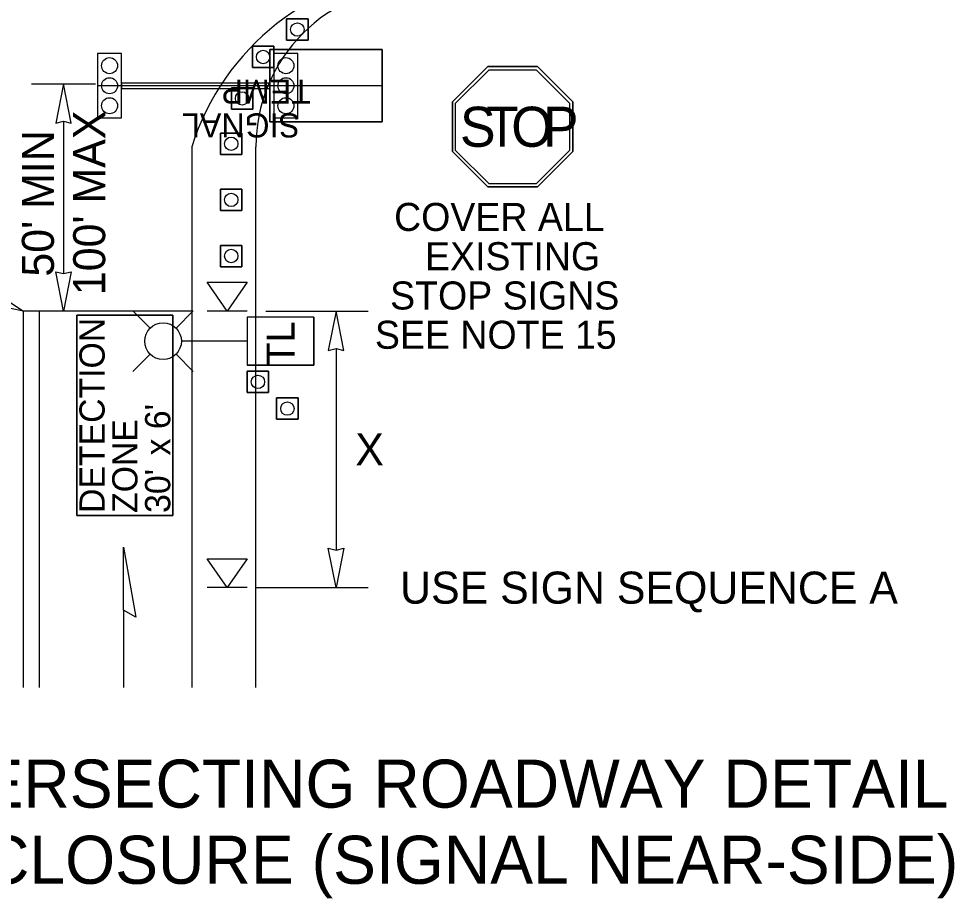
# Model space of a CAD drawing. Extents: x 99979.8 to 100075.7, y 99995 to 100010.7.
# Drawn here: x 100042.093 to 100044.428, y 100001.75 to 100003.944 of the extents above; entities that cross this region are included whole.
import ezdxf

# ---------------------------------------------------------------- set-up
doc = ezdxf.new("R2010")
doc.units = 0
for name, color, linetype in [('RD_ED_ShoulderPavedEdge', 7, 'Continuous'), ('RD_MK_LineDblYellowCenter', 7, 'Continuous'), ('RD_MK_LineEdgeWhite', 7, 'Continuous'), ('RD_MK_LineStop', 7, 'Continuous'), ('SH_DE_DetailHeading2Text', 7, 'Continuous'), ('TR_SN_ConstructionSigns', 7, 'Continuous'), ('TR_WZ_PortableLightStandard', 7, 'Continuous'), ('TR_WZ_PortableSignMountBlk-Org', 7, 'Continuous'), ('TR_WZ_PortableSignMountBlk-Wht', 7, 'Continuous'), ('TR_WZ_TempSignal', 7, 'Continuous'), ('TR_WZ_TrafficCone', 7, 'Continuous'), ('TR_WZ_WorkZoneDetails', 7, 'Continuous'), ('TR_WZ_WorkZoneTextCurrent', 7, 'Continuous')]:
    doc.layers.add(name, color=color, linetype=linetype)

msp = doc.modelspace()

# ---------------------------------------------------------------- linework, layer by layer
at = {"layer": 'RD_ED_ShoulderPavedEdge'}
msp.add_lwpolyline([(100042.685, 100002.2759), (100042.685, 100003.6249)], dxfattribs=at)
msp.add_arc((100043.085, 100003.6249), 0.4, 90, 180, dxfattribs=at)
at = {"layer": 'RD_MK_LineDblYellowCenter'}
for p, q in [((100042.105, 100002.2759), (100042.105, 100003.2149)), ((100042.145, 100002.2759), (100042.145, 100003.2149))]:
    msp.add_line(p, q, dxfattribs=at)
at = {"layer": 'RD_MK_LineEdgeWhite'}
msp.add_line((100042.525, 100003.6249), (100042.525, 100002.2759), dxfattribs=at)
msp.add_arc((100043.1265, 100003.4357), 0.6306, 93.7766, 162.5378, dxfattribs=at)
at = {"layer": 'RD_MK_LineStop'}
msp.add_line((100042.525, 100003.2149), (100042.105, 100003.2149), dxfattribs=at)
at = {"layer": 'TR_SN_ConstructionSigns'}
for p, q in [((100043.2637, 100003.8249), (100043.1758, 100003.7371)), ((100043.2637, 100003.8249), (100043.1758, 100003.7371)), ((100043.3879, 100003.8249), (100043.2637, 100003.8249)), ((100043.3879, 100003.8249), (100043.2637, 100003.8249)), ((100043.4758, 100003.7371), (100043.3879, 100003.8249)), ((100043.4758, 100003.7371), (100043.3879, 100003.8249)), ((100043.1836, 100003.7338), (100043.2669, 100003.8171)), ((100043.2669, 100003.8171), (100043.3847, 100003.8171)), ((100043.3847, 100003.8171), (100043.468, 100003.7338)), ((100043.1758, 100003.7371), (100043.1758, 100003.6128)), ((100043.1758, 100003.7371), (100043.1758, 100003.6128)), ((100043.1836, 100003.616), (100043.1836, 100003.7338)), ((100043.468, 100003.7338), (100043.468, 100003.616)), ((100043.4758, 100003.6128), (100043.4758, 100003.7371)), ((100043.4758, 100003.6128), (100043.4758, 100003.7371)), ((100043.1758, 100003.6128), (100043.2637, 100003.5249)), ((100043.1758, 100003.6128), (100043.2637, 100003.5249)), ((100043.2669, 100003.5327), (100043.1836, 100003.616)), ((100043.468, 100003.616), (100043.3847, 100003.5327)), ((100043.3879, 100003.5249), (100043.4758, 100003.6128)), ((100043.3879, 100003.5249), (100043.4758, 100003.6128)), ((100043.2637, 100003.5249), (100043.3879, 100003.5249)), ((100043.2637, 100003.5249), (100043.3879, 100003.5249)), ((100043.3847, 100003.5327), (100043.2669, 100003.5327))]:
    msp.add_line(p, q, dxfattribs=at)
msp.add_lwpolyline([(100043.2637, 100003.8249), (100043.3879, 100003.8249), (100043.4758, 100003.7371), (100043.4758, 100003.6128), (100043.3879, 100003.5249), (100043.2637, 100003.5249), (100043.1758, 100003.6128), (100043.1758, 100003.7371), (100043.2637, 100003.8249)], dxfattribs=at)
at = {"layer": 'TR_WZ_PortableLightStandard'}
for p, q in [((100042.4211, 100003.1723), (100042.378, 100003.2153)), ((100042.4857, 100003.1723), (100042.5288, 100003.2153)), ((100042.8295, 100003.1999), (100042.6636, 100003.1999)), ((100042.6636, 100003.1999), (100042.6636, 100003.0799)), ((100042.8295, 100003.1999), (100042.6636, 100003.1999)), ((100042.8295, 100003.1999), (100042.8295, 100003.0799)), ((100042.6636, 100003.1399), (100042.4992, 100003.1399)), ((100042.4211, 100003.1075), (100042.378, 100003.0645)), ((100042.4857, 100003.1075), (100042.5288, 100003.0645)), ((100042.8295, 100003.0799), (100042.6636, 100003.0799)), ((100042.6636, 100003.0799), (100042.8295, 100003.0799))]:
    msp.add_line(p, q, dxfattribs=at)
for points in [[(100042.6636, 100003.1999), (100042.6636, 100003.1399), (100042.6636, 100003.0799)], [(100042.8295, 100003.0799), (100042.8295, 100003.1399), (100042.8295, 100003.1999)]]:
    msp.add_lwpolyline(points, dxfattribs=at)
msp.add_circle((100042.4534, 100003.1399), 0.0457, dxfattribs=at)
msp.add_circle((100042.4534, 100003.1399), 0.0457, dxfattribs=at)
at = {"layer": 'TR_WZ_PortableSignMountBlk-Org'}
msp.add_line((100042.6636, 100002.5249), (100042.5636, 100002.5249), dxfattribs=at)
msp.add_lwpolyline([(100042.6137, 100002.5249), (100042.5636, 100002.5968), (100042.6636, 100002.5968)], close=True, dxfattribs=at)
at = {"layer": 'TR_WZ_PortableSignMountBlk-Wht'}
msp.add_line((100042.6636, 100003.2149), (100042.5636, 100003.2149), dxfattribs=at)
msp.add_lwpolyline([(100042.6137, 100003.2149), (100042.5636, 100003.2868), (100042.6636, 100003.2868)], close=True, dxfattribs=at)
at = {"layer": 'TR_WZ_TempSignal'}
for p, q in [((100042.72, 100003.8674), (100043.0002, 100003.8674)), ((100042.72, 100003.6873), (100042.72, 100003.8674)), ((100043.0002, 100003.8674), (100042.72, 100003.8674)), ((100042.72, 100003.8674), (100042.72, 100003.784)), ((100043.0002, 100003.8674), (100043.0002, 100003.6873)), ((100043.0002, 100003.6873), (100043.0002, 100003.8674)), ((100042.3497, 100003.8573), (100042.2898, 100003.8573)), ((100042.2898, 100003.8573), (100042.2898, 100003.6974)), ((100042.3497, 100003.6974), (100042.3497, 100003.8573)), ((100042.7899, 100003.8573), (100042.73, 100003.8573)), ((100042.73, 100003.8573), (100042.73, 100003.6974)), ((100042.7899, 100003.6974), (100042.7899, 100003.8573)), ((100043.0002, 100003.7773), (100042.2898, 100003.7773)), ((100042.72, 100003.784), (100042.3497, 100003.784)), ((100042.3497, 100003.784), (100042.3497, 100003.7707)), ((100042.72, 100003.7707), (100042.72, 100003.784)), ((100042.72, 100003.784), (100042.72, 100003.7707)), ((100042.3497, 100003.7707), (100042.72, 100003.7707)), ((100042.72, 100003.7707), (100042.72, 100003.6873)), ((100042.2898, 100003.6974), (100042.3497, 100003.6974)), ((100043.0002, 100003.6873), (100042.72, 100003.6873)), ((100042.72, 100003.6873), (100043.0002, 100003.6873)), ((100042.73, 100003.6974), (100042.7899, 100003.6974))]:
    msp.add_line(p, q, dxfattribs=at)
for points in [[(100042.3497, 100003.8573), (100042.2898, 100003.8573), (100042.2898, 100003.6974), (100042.3497, 100003.6974), (100042.3497, 100003.8573)], [(100042.7899, 100003.8573), (100042.73, 100003.8573), (100042.73, 100003.6974), (100042.7899, 100003.6974), (100042.7899, 100003.8573)]]:
    msp.add_lwpolyline(points, dxfattribs=at)
for centre in [(100042.3198, 100003.8273), (100042.3198, 100003.8273), (100042.76, 100003.8273), (100042.76, 100003.8273), (100042.3198, 100003.7773), (100042.3198, 100003.7773), (100042.76, 100003.7773), (100042.76, 100003.7773), (100042.3198, 100003.7274), (100042.3198, 100003.7274), (100042.76, 100003.7274), (100042.76, 100003.7274)]:
    msp.add_circle(centre, 0.02, dxfattribs=at)
at = {"layer": 'TR_WZ_TrafficCone'}
for points in [[(100042.7618, 100003.8907), (100042.7618, 100003.944), (100042.8152, 100003.944), (100042.8152, 100003.8907), (100042.7618, 100003.8907)], [(100042.8152, 100003.8907), (100042.8152, 100003.944), (100042.7618, 100003.944), (100042.7618, 100003.8907), (100042.8152, 100003.8907)], [(100042.6765, 100003.8224), (100042.6765, 100003.8757), (100042.7299, 100003.8757), (100042.7299, 100003.8224), (100042.6765, 100003.8224)], [(100042.7299, 100003.8224), (100042.7299, 100003.8757), (100042.6765, 100003.8757), (100042.6765, 100003.8224), (100042.7299, 100003.8224)], [(100042.6238, 100003.7187), (100042.6238, 100003.7721), (100042.6771, 100003.7721), (100042.6771, 100003.7187), (100042.6238, 100003.7187)], [(100042.6771, 100003.7187), (100042.6771, 100003.7721), (100042.6238, 100003.7721), (100042.6238, 100003.7187), (100042.6771, 100003.7187)], [(100042.5968, 100003.6057), (100042.5968, 100003.659), (100042.6501, 100003.659), (100042.6501, 100003.6057), (100042.5968, 100003.6057)], [(100042.6501, 100003.6057), (100042.6501, 100003.659), (100042.5968, 100003.659), (100042.5968, 100003.6057), (100042.6501, 100003.6057)], [(100042.5968, 100003.4657), (100042.5968, 100003.519), (100042.6501, 100003.519), (100042.6501, 100003.4657), (100042.5968, 100003.4657)], [(100042.6501, 100003.4657), (100042.6501, 100003.519), (100042.5968, 100003.519), (100042.5968, 100003.4657), (100042.6501, 100003.4657)], [(100042.5968, 100003.3257), (100042.5968, 100003.379), (100042.6501, 100003.379), (100042.6501, 100003.3257), (100042.5968, 100003.3257)], [(100042.6501, 100003.3257), (100042.6501, 100003.379), (100042.5968, 100003.379), (100042.5968, 100003.3257), (100042.6501, 100003.3257)], [(100042.6636, 100003.0116), (100042.6636, 100003.0649), (100042.7169, 100003.0649), (100042.7169, 100003.0116), (100042.6636, 100003.0116)], [(100042.7169, 100003.0116), (100042.7169, 100003.0649), (100042.6636, 100003.0649), (100042.6636, 100003.0116), (100042.7169, 100003.0116)], [(100042.7369, 100002.9449), (100042.7369, 100002.9983), (100042.7902, 100002.9983), (100042.7902, 100002.9449), (100042.7369, 100002.9449)], [(100042.7902, 100002.9449), (100042.7902, 100002.9983), (100042.7369, 100002.9983), (100042.7369, 100002.9449), (100042.7902, 100002.9449)]]:
    msp.add_lwpolyline(points, dxfattribs=at)
for centre in [(100042.7885, 100003.9174), (100042.7032, 100003.849), (100042.6505, 100003.7454), (100042.6234, 100003.6324), (100042.6234, 100003.4924), (100042.6234, 100003.3524), (100042.6902, 100003.0383), (100042.7636, 100002.9716)]:
    msp.add_circle(centre, 0.0167, dxfattribs=at)
at = {"layer": 'TR_WZ_WorkZoneDetails'}
for p, q in [((100043.1758, 100003.7371), (100043.2637, 100003.8249)), ((100043.2637, 100003.8249), (100043.1758, 100003.7371)), ((100043.2637, 100003.8249), (100043.2637, 100003.8249)), ((100043.2637, 100003.8249), (100043.3879, 100003.8249)), ((100043.3879, 100003.8249), (100043.2637, 100003.8249)), ((100043.3879, 100003.8249), (100043.4758, 100003.7371)), ((100043.4758, 100003.7371), (100043.3879, 100003.8249)), ((100042.125, 100003.7824), (100042.285, 100003.7824)), ((100043.1758, 100003.7371), (100043.1758, 100003.7371)), ((100043.1758, 100003.6128), (100043.1758, 100003.7371)), ((100043.1758, 100003.7371), (100043.1758, 100003.6128)), ((100043.4758, 100003.7371), (100043.4758, 100003.7371)), ((100043.4758, 100003.7371), (100043.4758, 100003.6128)), ((100043.4758, 100003.6128), (100043.4758, 100003.7371)), ((100042.205, 100003.6887), (100042.205, 100003.3087)), ((100043.1758, 100003.6128), (100043.1758, 100003.6128)), ((100043.2637, 100003.5249), (100043.1758, 100003.6128)), ((100043.1758, 100003.6128), (100043.2637, 100003.5249)), ((100043.4758, 100003.6128), (100043.3879, 100003.5249)), ((100043.3879, 100003.5249), (100043.4758, 100003.6128)), ((100043.4758, 100003.6128), (100043.4758, 100003.6128)), ((100043.2637, 100003.5249), (100043.2637, 100003.5249)), ((100043.3879, 100003.5249), (100043.2637, 100003.5249)), ((100043.2637, 100003.5249), (100043.3879, 100003.5249)), ((100043.3879, 100003.5249), (100043.3879, 100003.5249)), ((100042.7095, 100003.2149), (100042.965, 100003.2149)), ((100042.885, 100003.1212), (100042.885, 100002.6187)), ((100042.685, 100002.5249), (100042.965, 100002.5249)), ((100042.3545, 100002.4688), (100042.3545, 100002.2759))]:
    msp.add_line(p, q, dxfattribs=at)
for points in [[(100042.205, 100003.7824), (100042.1858, 100003.6841), (100042.205, 100003.6887), (100042.2243, 100003.6841)], [(100042.205, 100003.2149), (100042.1858, 100003.3132), (100042.205, 100003.3087), (100042.2243, 100003.3132)], [(100042.105, 100003.2149), (100042.0068, 100003.2344), (100042.0183, 100003.2505), (100042.0214, 100003.27)], [(100042.885, 100003.2149), (100042.8657, 100003.1166), (100042.885, 100003.1212), (100042.9043, 100003.1166)], [(100042.3545, 100002.626), (100042.3854, 100002.451), (100042.3545, 100002.4688)], [(100042.885, 100002.5249), (100042.8657, 100002.6232), (100042.885, 100002.6187), (100042.9043, 100002.6232)]]:
    msp.add_lwpolyline(points, close=True, dxfattribs=at)
for points in [[(100042.478, 100002.7049), (100042.478, 100003.2049), (100042.238, 100003.2049), (100042.238, 100002.7049), (100042.478, 100002.7049)], [(100042.238, 100002.7049), (100042.238, 100003.2049), (100042.478, 100003.2049), (100042.478, 100002.7049), (100042.238, 100002.7049)]]:
    msp.add_lwpolyline(points, dxfattribs=at)

# ---------------------------------------------------------------- texts
at = {"layer": 'SH_DE_DetailHeading2Text'}
for s, p in [('UNSIGNALIZED INTERSECTING ROADWAY DETAIL', (100040.5086, 100001.9759)), ('OPPOSITE OF LANE CLOSURE (SIGNAL NEAR-SIDE)', (100040.4077, 100001.7859))]:
    msp.add_text(s, height=0.12, rotation=360, dxfattribs=at).set_placement(p)
at = {"layer": 'TR_SN_ConstructionSigns'}
for s, p in [('COVER ALL', (100043.03, 100003.4149)), ('EXISTING', (100043.1072, 100003.3169)), ('STOP SIGNS', (100043.02, 100003.2189)), ('SEE NOTE 15', (100042.9821, 100003.1209))]:
    msp.add_text(s, height=0.07, dxfattribs=at).set_placement(p)
at = {"layer": 'TR_WZ_PortableLightStandard'}
msp.add_text('TL', height=0.07, rotation=90, dxfattribs=at).set_placement((100042.7816, 100003.0798))
at = {"layer": 'TR_WZ_TempSignal'}
for s, p in [('TEMP', (100042.8222, 100003.7923)), ('SIGNAL', (100042.795, 100003.7083))]:
    msp.add_text(s, height=0.06, rotation=180, dxfattribs=at).set_placement(p)
at = {"layer": 'TR_WZ_WorkZoneDetails'}
for s, p in [('S', (100043.1943, 100003.6249)), ('O', (100043.3223, 100003.6249)), ('T', (100043.2593, 100003.6249)), ('P', (100043.4013, 100003.6249))]:
    msp.add_text(s, height=0.1, dxfattribs=at).set_placement(p)
for s, p in [('DETECTION', (100042.3076, 100002.7113)), ("x 6'", (100042.4714, 100002.8548)), ('ZONE', (100042.3895, 100002.7113)), ("30'", (100042.4714, 100002.7113))]:
    msp.add_text(s, height=0.063, rotation=90, dxfattribs=at).set_placement(p)
at = {"layer": 'TR_WZ_WorkZoneTextCurrent'}
for s, p in [("100' MAX", (100042.309, 100003.2548)), ("50' MIN", (100042.181, 100003.3009))]:
    msp.add_text(s, height=0.08, rotation=90, dxfattribs=at).set_placement(p)
for s, p in [('X', (100042.9332, 100002.8299)), ('USE SIGN SEQUENCE A', (100043.045, 100002.4849))]:
    msp.add_text(s, height=0.08, dxfattribs=at).set_placement(p)

doc.saveas('drawing.dxf')
